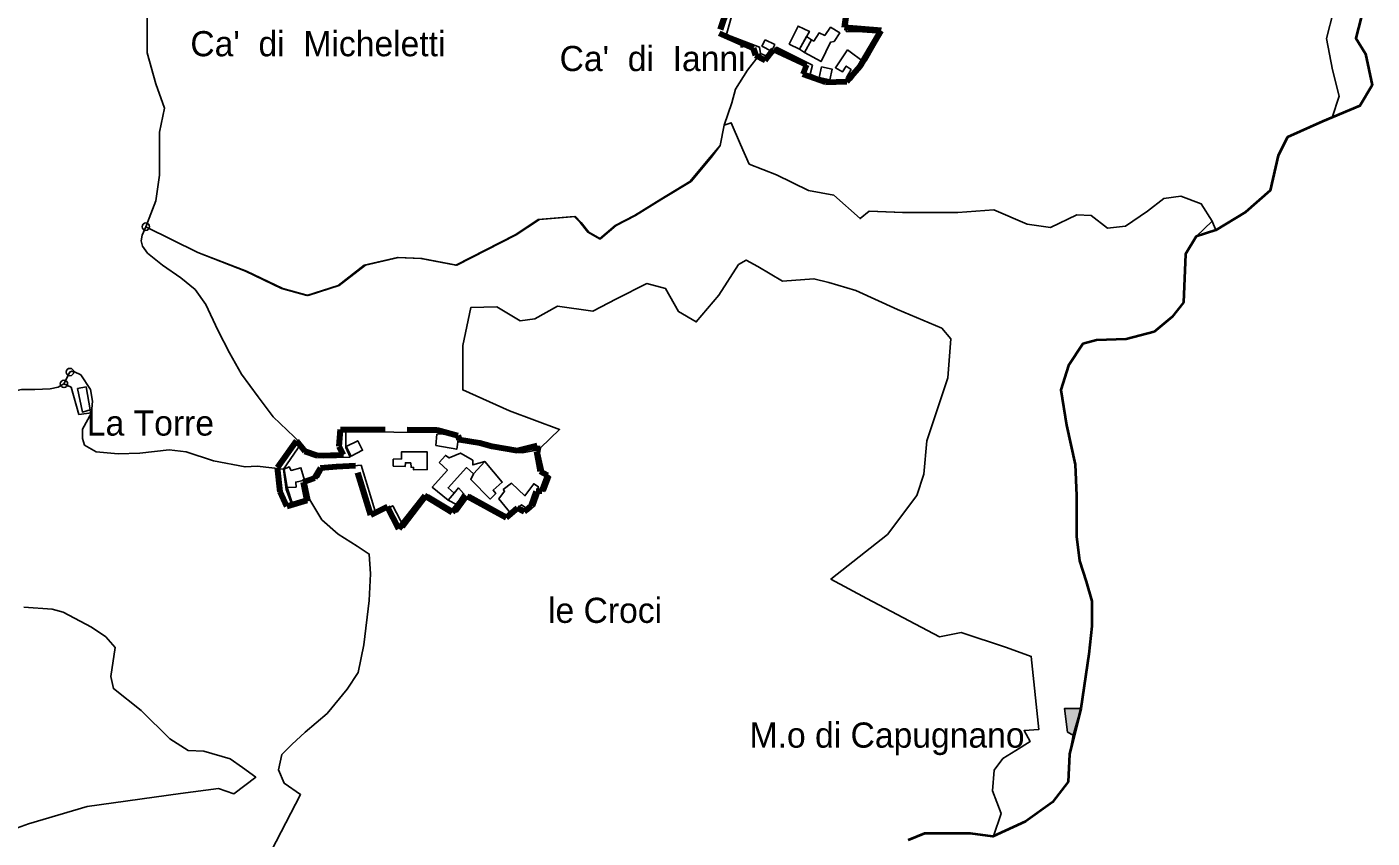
# Model space of a CAD drawing. Extents: x 645880 to 658994, y 884400 to 894744.
# Drawn here: x 655828 to 656737, y 889906 to 890454 of the extents above; entities that cross this region are included whole.
import ezdxf
from ezdxf.enums import TextEntityAlignment as Align

# ---------------------------------------------------------------- set-up
doc = ezdxf.new("R2010")
doc.units = 0
doc.header["$LTSCALE"] = 10
doc.header["$PDMODE"] = 32
doc.header["$PDSIZE"] = 5
doc.linetypes.add('MEDIUM_DASHED', pattern=[4.5, 3, -1.5])
for name, color, linetype, lineweight in [('1', 7, 'Continuous', 25), ('15', 7, 'MEDIUM_DASHED', 100), ('16', 7, 'Continuous', 25), ('18', 7, 'Continuous', 25), ('2', 7, 'Continuous', 25), ('59', 7, 'Continuous', 40)]:
    doc.layers.add(name, color=color, linetype=linetype, lineweight=lineweight)
doc.layers.add('60', color=7, linetype='Continuous')

msp = doc.modelspace()

# ---------------------------------------------------------------- hatches: boundary and pattern name
at = {"layer": '2'}
msp.add_hatch(color=256, dxfattribs=at).paths.add_polyline_path([(656540.21, 889993.78), (656529.21, 889993.78), (656531.21, 889977.78), (656534.92, 889975.8)])

# ---------------------------------------------------------------- linework, layer by layer
at = {"layer": '1'}
for points in [[(656316.6, 890482.09), (656310.86, 890480.17), (656304.84, 890463.75), (656300.81, 890449.21), (656323.09, 890440.57), (656323.73, 890436.19), (656329.95, 890433.47)], [(656405.68, 890449.96), (656389.24, 890451.06), (656381.68, 890451.17), (656386.34, 890484.41), (656353.4, 890482.51), (656349.21, 890475.84), (656345.83, 890476.36), (656329.38, 890483.21), (656326.8, 890477.93), (656316.6, 890482.09)], [(656354.89, 890447.83), (656350.13, 890439.21), (656353.4, 890437.01)], [(656353.4, 890437.01), (656358.19, 890445.47), (656354.89, 890447.83)], [(656358.78, 890428.46), (656357.27, 890422.36), (656362.33, 890420.38), (656370.51, 890418.44), (656378.23, 890418.08), (656384.89, 890418.35), (656395.29, 890431.71), (656405.68, 890449.96)], [(656329.95, 890433.47), (656333.04, 890437.25), (656334.58, 890440.49), (656358.78, 890428.46)], [(656017.88, 890166.56), (656020.06, 890164.92), (656028.24, 890163.19), (656046.45, 890163.62), (656043.58, 890170.13), (656043.59, 890180.57), (656108.44, 890180.23), (656121.7, 890176.32), (656121.71, 890174.05), (656138.19, 890171.11), (656145.34, 890169.19)], [(656007.34, 890130.86), (656003.18, 890141.62), (656001.38, 890155.44), (656013.48, 890172.74), (656017.88, 890166.56)], [(656162.91, 890166.55), (656168.91, 890167.65), (656172.89, 890168.76), (656175.1, 890169.8), (656174.54, 890166.31), (656177.25, 890153.19), (656181.91, 890150.26), (656178.32, 890140.81), (656174.74, 890140.48), (656171.02, 890130.5), (656166.92, 890126.96), (656162.21, 890129.46), (656154.56, 890122.95), (656127.43, 890138.05), (656118.8, 890126.3)], [(656145.34, 890169.19), (656157.83, 890166.92), (656162.91, 890166.55)], [(656028.64, 890156.19), (656027.57, 890154.57), (656025.23, 890149.99), (656016.81, 890146.45), (656019.2, 890134.68), (656007.34, 890130.86)], [(656053.9, 890158.24), (656049.04, 890157.74), (656030.53, 890156.73), (656028.64, 890156.19)], [(656118.8, 890126.3), (656099.75, 890137.94), (656083.05, 890115.95), (656075.32, 890130.77), (656064.01, 890124.84), (656053.9, 890158.24)]]:
    msp.add_lwpolyline(points, dxfattribs=at)
for points in [[(656350.13, 890439.21), (656343.19, 890442.63), (656349.15, 890454.85), (656356.76, 890451.16)], [(656358.19, 890445.47), (656353.4, 890437.01), (656364.68, 890430.82), (656371.09, 890444.03), (656373.44, 890444.46), (656377.23, 890450.22), (656371.09, 890454), (656367.11, 890448.45), (656363.33, 890450.16), (656359.75, 890444.62)], [(656326.97, 890445.59), (656324.72, 890441.24), (656331.16, 890437.91), (656333.41, 890442.26)], [(656382.5, 890438.66), (656374.34, 890426.61), (656379.1, 890423.8), (656381.65, 890427.76), (656384.89, 890425.45), (656381.82, 890420), (656384.89, 890418.35), (656393.91, 890430.08)], [(656364.99, 890427.36), (656372.21, 890425.66), (656370.51, 890418.44), (656363.29, 890420.14)], [(656105.14, 890179.16), (656104.5, 890171.44), (656118.51, 890168.87), (656119.75, 890177.1), (656108.2, 890179.35)], [(656043.87, 890170.68), (656047.19, 890164.25), (656054.93, 890168.24), (656051.61, 890174.67)], [(656075.64, 890162.13), (656075.64, 890157.54), (656083.74, 890157.3), (656083.85, 890159.74), (656087.5, 890159.68), (656087.62, 890156.71), (656089.34, 890156.64), (656089.4, 890154.92), (656098.57, 890155.2), (656098.6, 890167.05), (656081.25, 890167.23), (656081.25, 890162.39)], [(656106.7, 890160.02), (656112.23, 890154.69), (656101.96, 890143.33), (656112.68, 890134.53), (656116.75, 890139.15), (656112.67, 890142.87), (656125.12, 890156.51), (656129.81, 890152.23), (656137.45, 890160.71), (656129.32, 890158.35), (656129.32, 890161.51), (656121.04, 890166.37), (656113.41, 890163.1), (656110.92, 890164.78)], [(656129.81, 890152.23), (656127.93, 890148.44), (656141.1, 890135.24), (656144.9, 890138.93), (656143.1, 890141.22), (656149.29, 890146.62), (656137.45, 890160.71), (656137.45, 890160.71)], [(656001.87, 890155.51), (656005.32, 890156.96), (656006.56, 890154.61), (656013.19, 890156.41), (656015.68, 890147.91), (656009.74, 890146.73), (656010.01, 890143.35), (656003.94, 890143)], [(656003.94, 890143), (656010.01, 890143.35), (656009.74, 890146.73), (656015.68, 890147.91), (656019.2, 890134.68), (656007.67, 890131.46)], [(656112.68, 890134.53), (656118.34, 890131.63), (656123.09, 890139.07), (656119.73, 890142.77), (656116.75, 890139.15)], [(656149.79, 890141.8), (656150.81, 890140.69), (656146.96, 890135.49), (656155.04, 890125.58), (656162.32, 890131.33), (656165.84, 890128.91), (656169.94, 890132.45), (656173.75, 890143.52), (656170.5, 890145.59), (656164.62, 890137.54), (656155.44, 890145.93)]]:
    msp.add_lwpolyline(points, close=True, dxfattribs=at)
at = {"layer": '15'}
msp.add_lwpolyline([(656326.91, 890431.81), (656332.62, 890438.94), (656354.72, 890428.62), (656352.4, 890422.3), (656367.55, 890416.83), (656382.07, 890417.25), (656391.12, 890427.78), (656405.22, 890451.78), (656380.39, 890453.89), (656385.02, 890486.31), (656349.54, 890484.92), (656345.25, 890478.1), (656326.1, 890485.68), (656322.73, 890481.26), (656315.36, 890484.21), (656306.1, 890480.84), (656295.79, 890450.1), (656318.73, 890439.78), (656320.46, 890435.07)], close=True, dxfattribs=at)
for points in [[(656003.7, 890130.18), (655999.29, 890140.16), (655997.35, 890156.49), (656010.17, 890174.64), (656015.87, 890167.64), (656024.54, 890164.65), (656042.03, 890165.17), (656039.05, 890170.74), (656040.08, 890182.28), (656105.25, 890182.08), (656119.22, 890178.13), (656120.25, 890175.54), (656134.11, 890173.21), (656142.15, 890170.88), (656159.37, 890168.16), (656172.84, 890171.53), (656172.46, 890167.64), (656174.92, 890154.16), (656179.84, 890151.44), (656175.82, 890140.68), (656172.2, 890140.29), (656168.87, 890130.79), (656164.08, 890126.52), (656159.37, 890129.02), (656151.96, 890122.53), (656124.4, 890137.57), (656115.46, 890126.16)], [(656115.46, 890126.16), (656096.94, 890137.44), (656079.45, 890115.15), (656071.8, 890129.92), (656060.41, 890124.35), (656050.17, 890157.79), (656037.24, 890157.01), (656026.5, 890156.23), (656022.35, 890149.36), (656014.84, 890146.64), (656017.17, 890134.33), (656003.7, 890130.18)]]:
    msp.add_lwpolyline(points, dxfattribs=at)
at = {"layer": '16'}
for p, q in [((656386.34, 890484.41), (656381.68, 890451.17)), ((655908.48, 890319.27), (655943.54, 890301.82))]:
    msp.add_line(p, q, dxfattribs=at)
for points in [[(655915.26, 890336.66), (655917.59, 890354.1), (655917.59, 890383.15), (655921.07, 890399.43), (655915.26, 890415.7), (655909.46, 890436.62), (655909.46, 890463.36), (655916.43, 890474.98), (655930.3, 890491.47), (655928.97, 890534.53), (655925.01, 890539.27), (655915.12, 890553.65), (655924.48, 890560.83), (655924.68, 890569.8), (655913.39, 890572.31), (655899.22, 890571.74)], [(655930.3, 890491.47), (655916.43, 890474.98), (655909.46, 890463.36), (655909.46, 890436.62), (655915.26, 890415.7), (655921.07, 890399.43), (655917.59, 890383.15), (655917.59, 890354.1), (655915.26, 890336.66), (655908.48, 890319.27)], [(656300.81, 890449.21), (656304.84, 890463.75), (656310.86, 890480.17), (656315.7, 890481.79)], [(656628.85, 890322.89), (656631.31, 890316.99), (656651.47, 890328.97), (656668.04, 890343.7), (656673.48, 890367.43), (656679.82, 890379.74), (656709.93, 890393.03), (656714.71, 890407.54), (656710.11, 890425.3), (656706.17, 890446.36), (656710.77, 890464.77)], [(656381.68, 890451.17), (656389.24, 890451.06), (656405.68, 890449.96), (656395.29, 890431.71), (656384.89, 890418.35), (656378.23, 890418.08), (656370.51, 890418.44), (656362.33, 890420.38)], [(656299.25, 890387.92), (656304.42, 890402.91), (656306.74, 890412.21), (656314.87, 890425), (656323.73, 890436.19), (656323.09, 890440.57), (656300.81, 890449.21)], [(656323.73, 890436.19), (656314.87, 890425), (656306.74, 890412.21), (656304.42, 890402.91), (656299.25, 890387.92), (656303.99, 890389.48), (656310.2, 890374.73), (656316.11, 890361.58), (656334.51, 890354.34), (656356.19, 890343.82), (656373.27, 890340.53), (656391.01, 890324.74), (656397.13, 890329.76), (656419.63, 890328.76), (656457.01, 890328.77), (656481.33, 890330.6), (656503.92, 890321.01), (656519.69, 890318.66), (656537.38, 890327.19), (656547.2, 890326.77), (656558.07, 890318.23), (656570.28, 890319.72), (656585.2, 890329.74), (656596.28, 890338.27), (656607.72, 890339.94), (656621.52, 890334.68), (656628.85, 890322.89), (656618.07, 890312.67), (656628.85, 890322.89)], [(656358.78, 890428.46), (656334.58, 890440.49), (656333.04, 890437.25), (656329.95, 890433.47), (656323.73, 890436.19)], [(656362.33, 890420.38), (656357.27, 890422.36), (656358.78, 890428.46)], [(655943.54, 890301.82), (655975.79, 890289.22), (656000.2, 890277.48), (656017.28, 890272.88), (656038.31, 890279.45), (656056.04, 890293.27), (656078.38, 890298.53), (656094.15, 890297.87), (656117.8, 890293.27), (656157.88, 890313.66), (656173.56, 890324.11), (656197.87, 890326.08), (656201.81, 890322.13), (656207.06, 890315.56), (656214.95, 890310.95), (656225.46, 890320.16), (656238.6, 890326.74), (656256.34, 890337.92), (656276.05, 890349.76), (656289.84, 890366.21), (656296.55, 890374.11), (656299.25, 890387.92)], [(655871.69, 890193.57), (655865.64, 890182.46), (655865.64, 890176.2), (655866.98, 890171.73), (655875.02, 890167.26), (655889.77, 890165.92), (655904.51, 890166.37), (655924.17, 890168.6), (655935.78, 890167.26), (655954.1, 890161), (655975.54, 890156.98), (655983.58, 890157.43), (656001.38, 890155.44), (656013.48, 890172.74), (655994.56, 890190.9), (655984.25, 890204.39), (655973.13, 890219.66), (655965.03, 890234.05), (655957.19, 890249.28), (655949.11, 890266.79), (655941.79, 890276.94), (655932.18, 890284.8), (655919.65, 890293.34), (655909.65, 890301.36), (655906.19, 890306.07), (655905.35, 890309.6), (655905.97, 890313.53), (655908.48, 890319.27), (655915.26, 890336.66)], [(656446.22, 890250.74), (656416.41, 890263.23), (656388.13, 890276.16), (656369.88, 890281.53), (656359.83, 890284.11), (656338.7, 890282.35), (656321.96, 890292.36), (656313.95, 890296.64), (656308.88, 890293.71), (656295.67, 890273.02), (656280.32, 890254.89), (656268.38, 890261.93), (656259.63, 890277.59), (656247.02, 890280.85), (656226.56, 890270.5), (656210.4, 890262.14), (656186.52, 890265.56), (656171.18, 890257.02), (656161.37, 890255.74), (656145.6, 890265.12), (656128.12, 890264.69), (656122.62, 890238.96), (656122.62, 890209.01), (656154.11, 890194.82), (656187.98, 890182.2), (656175.1, 890169.8), (656174.54, 890166.31), (656177.25, 890153.19), (656181.91, 890150.26), (656178.32, 890140.81), (656174.74, 890140.48), (656171.02, 890130.5), (656166.92, 890126.96), (656162.21, 890129.46), (656154.56, 890122.95), (656127.43, 890138.05), (656118.8, 890126.3)], [(656423.4, 889904.82), (656434.46, 889909.24), (656465.67, 889909.24), (656481.08, 889907.59), (656486.33, 889922.71), (656480.47, 889938.17), (656481.6, 889951.99), (656487.46, 889959.93), (656496.35, 889965.42), (656505.99, 889971.48), (656501.83, 889978.86), (656511.86, 889979.61), (656506.66, 890028.91), (656490.02, 890034.97), (656459.39, 890045.18), (656444.63, 890042.16), (656395.67, 890068.07), (656371.36, 890081.22), (656409.64, 890111.39), (656429.29, 890137.68), (656434.03, 890152.14), (656436.06, 890174.49), (656450.29, 890217.22), (656452.32, 890243.51), (656446.22, 890250.74)], [(655788.71, 890201.09), (655797.74, 890203.02), (655809.8, 890206.15), (655824.54, 890209.28), (655833.48, 890209.28), (655843.75, 890209.73), (655849.31, 890210.78), (655853.15, 890213.11), (655857.19, 890221.07), (655858.39, 890221.77), (655860.29, 890221.17), (655864.49, 890219.17), (655870.99, 890209.17), (655872.49, 890201.37), (655871.69, 890193.57)], [(655843.75, 890209.73), (655833.48, 890209.28), (655824.54, 890209.28)], [(656001.38, 890155.44), (655983.58, 890157.43), (655975.54, 890156.98), (655954.1, 890161), (655935.78, 890167.26), (655924.17, 890168.6), (655904.51, 890166.37), (655889.77, 890165.92), (655875.02, 890167.26), (655866.98, 890171.73), (655865.64, 890176.2), (655865.64, 890182.46), (655871.69, 890193.57), (655863.29, 890192.4), (655857.95, 890210.78), (655853.15, 890213.11), (655849.31, 890210.78), (655843.75, 890209.73)], [(656007.34, 890130.86), (656003.18, 890141.62), (656001.38, 890155.44)], [(656030.53, 890156.73), (656028.64, 890156.19), (656027.57, 890154.57), (656025.23, 890149.99), (656016.81, 890146.45), (656019.2, 890134.68)], [(656053.9, 890158.24), (656049.04, 890157.74), (656030.53, 890156.73)], [(656099.75, 890137.94), (656083.05, 890115.95), (656083.05, 890115.95), (656075.32, 890130.77), (656064.01, 890124.84), (656053.9, 890158.24)], [(656051.22, 890103.35), (656038.51, 890111.58), (656027.3, 890121.3), (656019.2, 890134.68), (656007.34, 890130.86)], [(656019.2, 890134.68), (656027.3, 890121.3), (656038.51, 890111.58), (656051.22, 890103.35)], [(656118.8, 890126.3), (656104.74, 890134.7), (656099.75, 890137.94)], [(655940.56, 889851.1), (655953.74, 889861.89), (655963.33, 889869.09), (655980.11, 889872.08), (656013.06, 889935.64), (656001.89, 889943.31), (655998.15, 889952.29), (656000.39, 889962.76), (656007.12, 889969.49), (656016.09, 889977.71), (656031.04, 889990.43), (656044.49, 890006.88), (656051.97, 890018.1), (656055.7, 890036.79), (656059.44, 890066.71), (656060.19, 890084.66), (656059.44, 890098.12), (656051.22, 890103.35)], [(656051.22, 890103.35), (656059.44, 890098.12), (656060.19, 890084.66), (656059.44, 890066.71), (656055.7, 890036.79), (656051.97, 890018.1), (656044.49, 890006.88), (656031.04, 889990.43), (656016.09, 889977.71), (656007.12, 889969.49), (656000.39, 889962.76), (655998.15, 889952.29), (656001.89, 889943.31), (656013.06, 889935.64)], [(655826.07, 890062.18), (655845.12, 890060.86), (655852.6, 890058.81), (655871.86, 890048.68), (655881.43, 890042.24), (655887.7, 890034.95), (655884.72, 890015.35), (655886.58, 890007.18), (655905.41, 889992.33), (655924.79, 889973.26), (655937.05, 889965.45), (655947.63, 889964.85), (655965.52, 889959.78), (655973.73, 889953.86), (655982.68, 889947.31), (655967.88, 889936.12), (655957.52, 889939.67), (655931.91, 889936.42), (655868.75, 889927.65), (655829.16, 889915.85), (655811.93, 889909.51)], [(656013.06, 889935.64), (655980.11, 889872.08)]]:
    msp.add_lwpolyline(points, dxfattribs=at)
msp.add_point((655908.48, 890319.27), dxfattribs=at)
at = {"layer": '18'}
for points in [[(656729.69, 890460.64), (656726.07, 890446.58), (656732.41, 890436.03), (656736.94, 890414.93), (656728.79, 890400.87), (656709.93, 890393.03), (656714.71, 890407.54), (656710.11, 890425.3), (656706.17, 890446.36), (656710.77, 890464.77)], [(655908.48, 890319.27), (655943.54, 890301.82), (655976.58, 890289.23), (656000.99, 890277.49), (656018.07, 890272.89), (656039.1, 890279.46), (656056.83, 890293.28), (656079.17, 890298.54), (656094.94, 890297.88), (656118.59, 890293.28), (656158.67, 890313.67), (656174.35, 890324.12), (656198.66, 890326.09), (656202.6, 890322.14), (656207.85, 890315.57), (656215.74, 890310.96), (656226.25, 890320.17), (656239.39, 890326.75), (656257.13, 890337.93), (656276.84, 890349.77), (656290.63, 890366.22), (656296.55, 890374.11), (656299.25, 890387.92), (656303.99, 890389.48), (656310.2, 890374.73), (656316.11, 890361.58), (656334.51, 890354.34), (656356.19, 890343.82), (656373.27, 890340.53), (656391.01, 890324.74), (656397.13, 890329.76), (656420.42, 890328.77), (656457.01, 890328.77), (656481.33, 890330.6), (656503.92, 890321.01), (656519.69, 890318.66), (656537.38, 890327.19), (656547.2, 890326.77), (656558.07, 890318.23), (656570.28, 890319.73)], [(656570.28, 890319.73), (656585.2, 890329.75), (656596.28, 890338.28), (656607.72, 890339.94), (656621.52, 890334.68), (656628.85, 890322.89), (656618.07, 890312.67), (656610.91, 890300.68), (656609.45, 890268.12), (656601.92, 890258.26), (656589.72, 890248.26), (656570.87, 890243.21), (656550.71, 890242.58), (656541.6, 890240.05), (656531.85, 890225.54), (656526.64, 890209.14), (656530.55, 890185.17), (656536.4, 890158.67), (656537.24, 890137.63), (656537.24, 890109.88), (656539.19, 890093.48), (656543.74, 890079.6), (656547.64, 890066.35), (656547.64, 890049.32), (656545.69, 890030.39), (656540.21, 889993.78), (656529.21, 889993.78), (656531.21, 889977.78), (656534.92, 889975.8), (656532.28, 889961.64), (656531.71, 889944.23), (656521.12, 889930.41), (656502.78, 889917.36), (656481.08, 889907.59), (656486.33, 889922.71), (656480.47, 889938.17), (656481.6, 889951.99), (656487.46, 889959.93), (656496.35, 889965.42), (656505.99, 889971.48)], [(656043.58, 890170.13), (656046.45, 890163.62), (656028.24, 890163.19), (656020.06, 890164.92), (656017.88, 890166.56), (656013.48, 890172.74), (655994.56, 890190.9), (655984.25, 890204.39), (655973.13, 890219.66), (655965.03, 890234.05), (655957.19, 890249.28), (655949.11, 890266.79), (655941.79, 890276.94), (655932.18, 890284.8), (655919.65, 890293.34), (655909.65, 890301.36), (655906.19, 890306.07), (655905.35, 890309.6), (655905.97, 890313.53), (655908.48, 890319.27)], [(656505.99, 889971.48), (656501.83, 889978.86), (656511.86, 889979.61), (656506.66, 890028.91), (656490.02, 890034.97), (656459.39, 890045.18), (656444.63, 890042.16), (656395.67, 890068.07), (656371.36, 890081.22), (656409.64, 890111.39), (656429.29, 890137.68), (656434.03, 890152.14), (656436.06, 890174.49), (656450.29, 890217.22), (656452.32, 890243.51), (656446.22, 890250.74), (656416.41, 890263.23), (656388.13, 890276.17), (656369.88, 890281.53), (656359.83, 890284.11), (656338.7, 890282.35), (656321.96, 890292.37), (656313.95, 890296.65), (656308.88, 890293.71), (656295.67, 890273.02), (656280.32, 890254.89), (656268.38, 890261.93), (656259.63, 890277.59), (656247.02, 890280.86), (656226.56, 890270.5), (656210.4, 890262.14), (656186.52, 890265.57), (656171.18, 890257.02), (656161.37, 890255.74), (656145.6, 890265.12), (656128.12, 890264.69), (656122.62, 890238.96), (656122.62, 890209.01), (656154.11, 890194.82), (656187.98, 890182.2)], [(656172.89, 890168.76), (656168.91, 890167.65), (656162.91, 890166.55), (656157.83, 890166.92), (656145.34, 890169.19), (656138.19, 890171.11), (656121.71, 890174.05), (656121.7, 890176.32), (656108.44, 890180.23), (656043.59, 890180.57), (656043.58, 890170.13)], [(656187.98, 890182.2), (656175.1, 890169.8), (656172.89, 890168.76)], [(655826.07, 890062.18), (655845.12, 890060.86), (655852.6, 890058.82), (655871.86, 890048.69), (655881.43, 890042.25), (655887.7, 890034.95), (655884.72, 890015.35), (655886.58, 890007.18), (655905.41, 889992.33), (655924.79, 889973.26), (655937.05, 889965.45), (655947.63, 889964.85), (655965.52, 889959.78), (655973.73, 889953.86), (655982.68, 889947.31), (655967.88, 889936.12), (655957.52, 889939.67), (655931.91, 889936.42), (655868.75, 889927.65), (655829.16, 889915.85), (655811.93, 889909.51)]]:
    msp.add_lwpolyline(points, dxfattribs=at)
at = {"layer": '2'}
msp.add_line((655853.15, 890213.11), (655857.95, 890210.78), dxfattribs=at)
msp.add_lwpolyline([(655857.95, 890210.78), (655863.29, 890192.4), (655871.69, 890193.57), (655872.49, 890201.37), (655870.99, 890209.17), (655864.49, 890219.17), (655860.29, 890221.17), (655858.39, 890221.77), (655857.19, 890221.07)], dxfattribs=at)
for points in [[(655862.3, 890210.05), (655868.04, 890211.02), (655870.95, 890195.57), (655865.57, 890194.07)], [(656540.21, 889993.78), (656529.21, 889993.78), (656531.21, 889977.78), (656534.92, 889975.8)]]:
    msp.add_lwpolyline(points, close=True, dxfattribs=at)
for p in [(655857.19, 890221.07), (655853.15, 890213.11)]:
    msp.add_point(p, dxfattribs=at)
at = {"layer": '59'}
msp.add_lwpolyline([(656729.66, 890460.61), (656726.04, 890446.55), (656732.38, 890436), (656736.91, 890414.9), (656728.76, 890400.84), (656703.38, 890390.29), (656679.82, 890379.74), (656673.48, 890367.43), (656668.04, 890343.7), (656651.47, 890328.97), (656631.31, 890316.99), (656618.07, 890312.67), (656610.91, 890300.68), (656609.45, 890268.12), (656601.92, 890258.26), (656589.69, 890248.23), (656570.84, 890243.18), (656550.68, 890242.55), (656541.57, 890240.02), (656531.82, 890225.51), (656526.61, 890209.11), (656530.52, 890185.14), (656536.37, 890158.64), (656537.21, 890137.6), (656537.21, 890109.85), (656539.16, 890093.45), (656543.71, 890079.57), (656547.61, 890066.32), (656547.61, 890049.29), (656545.66, 890030.36), (656540.21, 889993.78), (656532.42, 889962.84), (656531.71, 889944.23), (656521.12, 889930.41), (656502.78, 889917.36), (656480.63, 889907.35), (656465.67, 889909.24), (656434.46, 889909.24), (656423.4, 889904.82)], dxfattribs=at)

# ---------------------------------------------------------------- texts
at = {"layer": '60'}
for s, p in [("Ca'  di  Micheletti", (656024.74, 890434.4)), ("Ca'  di  Ianni", (656250.84, 890424.39)), ('La Torre', (655911.58, 890178.12)), ('le Croci', (656218.72, 890051.59)), ('M.o di Capugnano', (656409.26, 889967.31))]:
    msp.add_text(s, height=17, dxfattribs=at).set_placement(p, align=Align.CENTER)

doc.saveas('drawing.dxf')
